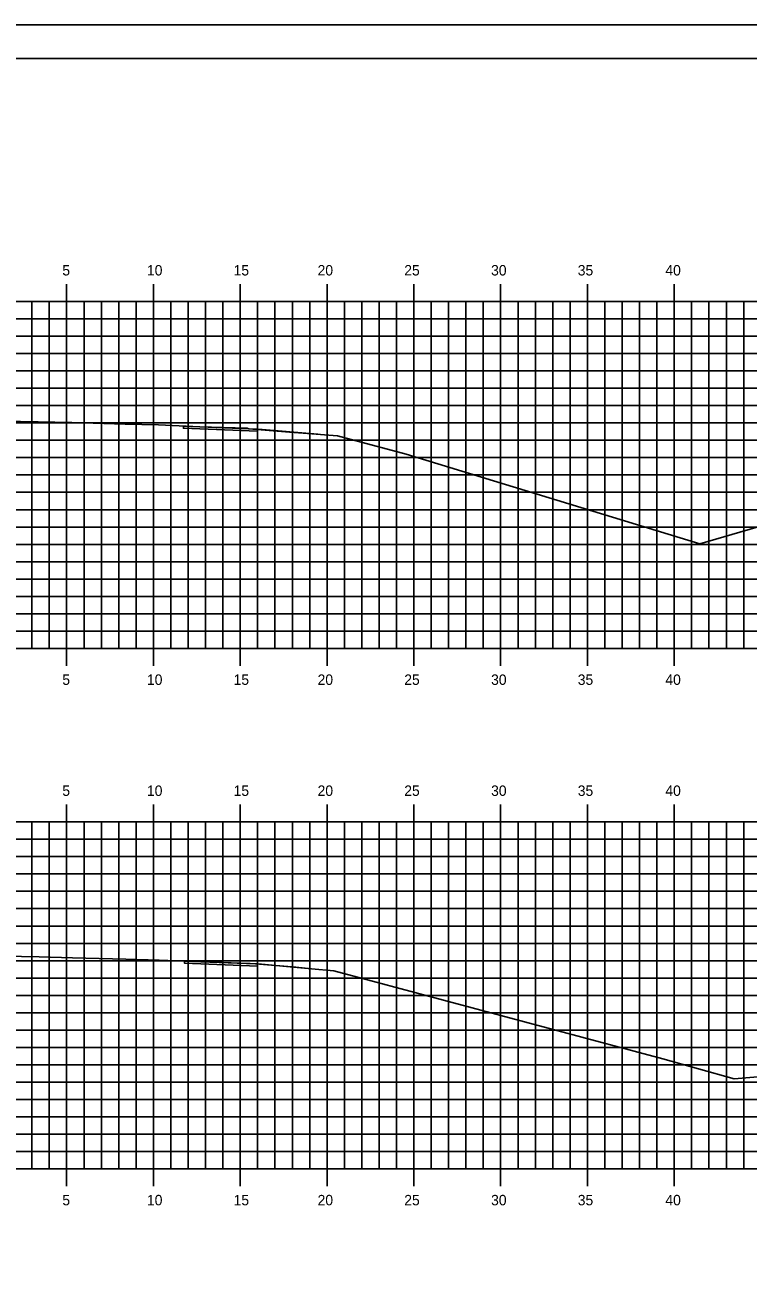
# Model space of a CAD drawing. Extents: x 1168600 to 1177589, y 610178 to 611246.
# Drawn here: x 1177281.8 to 1177323.4, y 610306.8 to 610378.7 of the extents above; entities that cross this region are included whole.
import ezdxf

# ---------------------------------------------------------------- set-up
doc = ezdxf.new("R2010")
doc.units = 0
for name, color, linetype in [('_Construction', 7, 'Continuous'), ('_Station Equation', 7, 'Continuous'), ('D_Roadway_Edge_TW', 7, 'Continuous'), ('D_Text_Standard', 7, 'Continuous'), ('H_V ANNOTATION', 7, 'Continuous'), ('MAJOR', 7, 'Continuous'), ('MINOR', 7, 'Continuous')]:
    doc.layers.add(name, color=color, linetype=linetype)

msp = doc.modelspace()

# ---------------------------------------------------------------- linework, layer by layer
at = {"layer": '_Construction'}
msp.add_line((1177364.168, 610376.801), (1177204.168, 610376.801), dxfattribs=at)
msp.add_lwpolyline([(1177196.074, 610268.742), (1177366.074, 610268.742), (1177366.074, 610378.742), (1177196.074, 610378.742)], close=True, dxfattribs=at)
at = {"layer": '_Station Equation'}
for points in [[(1177279.464, 610355.93), (1177282.534, 610355.863), (1177284.464, 610355.818), (1177287.54, 610355.736), (1177289.464, 610355.684), (1177291.831, 610355.585), (1177294.557, 610355.498), (1177294.667, 610355.465), (1177297.001, 610355.274), (1177298.051, 610355.193), (1177299.771, 610355.064), (1177303.725, 610354.005), (1177320.634, 610348.828), (1177331.513, 610352.01), (1177333.985, 610352.632), (1177338.786, 610353.459), (1177349.168, 610355.791)], [(1177279.503, 610325.085), (1177282.58, 610325.016), (1177284.503, 610324.972), (1177287.586, 610324.887), (1177289.503, 610324.835), (1177292.005, 610324.737), (1177294.736, 610324.649), (1177295.042, 610324.618), (1177297.37, 610324.419), (1177298.278, 610324.323), (1177299.564, 610324.223), (1177318.5, 610319.153), (1177322.626, 610317.983), (1177324.882, 610318.18), (1177335.048, 610320.751), (1177340.269, 610321.981), (1177349.168, 610323.258)]]:
    msp.add_lwpolyline(points, dxfattribs=at)
at = {"layer": 'D_Roadway_Edge_TW'}
for points in [[(1177290.898, 610355.624), (1177294.667, 610355.465), (1177295.168, 610355.443), (1177295.168, 610355.318), (1177290.898, 610355.499), (1177290.898, 610355.624)], [(1177290.898, 610355.624), (1177294.667, 610355.465), (1177295.168, 610355.443), (1177295.168, 610355.318), (1177290.898, 610355.499), (1177290.898, 610355.624)], [(1177290.958, 610324.778), (1177295.042, 610324.618), (1177295.168, 610324.613), (1177295.168, 610324.488), (1177290.958, 610324.653), (1177290.958, 610324.778)], [(1177290.958, 610324.778), (1177295.042, 610324.618), (1177295.168, 610324.613), (1177295.168, 610324.488), (1177290.958, 610324.653), (1177290.958, 610324.778)]]:
    msp.add_lwpolyline(points, dxfattribs=at)
at = {"layer": 'D_Text_Standard'}
for points in [[(1177290.898, 610355.624), (1177290.902, 610355.624), (1177294.668, 610355.465), (1177294.673, 610355.464), (1177295.168, 610355.443), (1177295.202, 610355.443), (1177298.637, 610355.149)], [(1177290.958, 610324.778), (1177291.906, 610324.741), (1177295.043, 610324.618), (1177295.043, 610324.618), (1177295.168, 610324.613), (1177295.172, 610324.613), (1177298.693, 610324.291)]]:
    msp.add_lwpolyline(points, dxfattribs=at)
at = {"layer": 'MAJOR'}
for p, q in [((1177284.168, 610363.803), (1177284.168, 610362.801)), ((1177289.168, 610363.803), (1177289.168, 610362.801)), ((1177294.168, 610363.803), (1177294.168, 610362.801)), ((1177299.168, 610363.803), (1177299.168, 610362.801)), ((1177304.168, 610363.803), (1177304.168, 610362.801)), ((1177309.168, 610363.803), (1177309.168, 610362.801)), ((1177314.168, 610363.803), (1177314.168, 610362.801)), ((1177319.168, 610363.803), (1177319.168, 610362.801)), ((1177209.168, 610362.801), (1177349.168, 610362.801)), ((1177209.168, 610362.801), (1177349.168, 610362.801)), ((1177284.168, 610342.801), (1177284.168, 610362.801)), ((1177289.168, 610342.801), (1177289.168, 610362.801)), ((1177294.168, 610342.801), (1177294.168, 610362.801)), ((1177299.168, 610342.801), (1177299.168, 610362.801)), ((1177304.168, 610342.801), (1177304.168, 610362.801)), ((1177309.168, 610342.801), (1177309.168, 610362.801)), ((1177314.168, 610342.801), (1177314.168, 610362.801)), ((1177319.168, 610342.801), (1177319.168, 610362.801)), ((1177209.168, 610357.801), (1177349.168, 610357.801)), ((1177209.168, 610352.801), (1177349.168, 610352.801)), ((1177209.168, 610347.801), (1177349.168, 610347.801)), ((1177209.168, 610342.801), (1177349.168, 610342.801)), ((1177209.168, 610342.801), (1177349.168, 610342.801)), ((1177284.168, 610341.799), (1177284.168, 610342.801)), ((1177289.168, 610341.799), (1177289.168, 610342.801)), ((1177294.168, 610341.799), (1177294.168, 610342.801)), ((1177299.168, 610341.799), (1177299.168, 610342.801)), ((1177304.168, 610341.799), (1177304.168, 610342.801)), ((1177309.168, 610341.799), (1177309.168, 610342.801)), ((1177314.168, 610341.799), (1177314.168, 610342.801)), ((1177319.168, 610341.799), (1177319.168, 610342.801)), ((1177284.168, 610333.803), (1177284.168, 610332.801)), ((1177289.168, 610333.803), (1177289.168, 610332.801)), ((1177294.168, 610333.803), (1177294.168, 610332.801)), ((1177299.168, 610333.803), (1177299.168, 610332.801)), ((1177304.168, 610333.803), (1177304.168, 610332.801)), ((1177309.168, 610333.803), (1177309.168, 610332.801)), ((1177314.168, 610333.803), (1177314.168, 610332.801)), ((1177319.168, 610333.803), (1177319.168, 610332.801)), ((1177209.168, 610332.801), (1177349.168, 610332.801)), ((1177209.168, 610332.801), (1177349.168, 610332.801)), ((1177284.168, 610312.801), (1177284.168, 610332.801)), ((1177289.168, 610312.801), (1177289.168, 610332.801)), ((1177294.168, 610312.801), (1177294.168, 610332.801)), ((1177299.168, 610312.801), (1177299.168, 610332.801)), ((1177304.168, 610312.801), (1177304.168, 610332.801)), ((1177309.168, 610312.801), (1177309.168, 610332.801)), ((1177314.168, 610312.801), (1177314.168, 610332.801)), ((1177319.168, 610312.801), (1177319.168, 610332.801)), ((1177209.168, 610327.801), (1177349.168, 610327.801)), ((1177209.168, 610322.801), (1177349.168, 610322.801)), ((1177209.168, 610317.801), (1177349.168, 610317.801)), ((1177209.168, 610312.801), (1177349.168, 610312.801)), ((1177209.168, 610312.801), (1177349.168, 610312.801)), ((1177284.168, 610311.799), (1177284.168, 610312.801)), ((1177289.168, 610311.799), (1177289.168, 610312.801)), ((1177294.168, 610311.799), (1177294.168, 610312.801)), ((1177299.168, 610311.799), (1177299.168, 610312.801)), ((1177304.168, 610311.799), (1177304.168, 610312.801)), ((1177309.168, 610311.799), (1177309.168, 610312.801)), ((1177314.168, 610311.799), (1177314.168, 610312.801)), ((1177319.168, 610311.799), (1177319.168, 610312.801))]:
    msp.add_line(p, q, dxfattribs=at)
at = {"layer": 'MINOR'}
for p, q in [((1177282.168, 610342.801), (1177282.168, 610362.801)), ((1177283.168, 610342.801), (1177283.168, 610362.801)), ((1177285.168, 610342.801), (1177285.168, 610362.801)), ((1177286.168, 610342.801), (1177286.168, 610362.801)), ((1177287.168, 610342.801), (1177287.168, 610362.801)), ((1177288.168, 610342.801), (1177288.168, 610362.801)), ((1177290.168, 610342.801), (1177290.168, 610362.801)), ((1177291.168, 610342.801), (1177291.168, 610362.801)), ((1177292.168, 610342.801), (1177292.168, 610362.801)), ((1177293.168, 610342.801), (1177293.168, 610362.801)), ((1177295.168, 610342.801), (1177295.168, 610362.801)), ((1177296.168, 610342.801), (1177296.168, 610362.801)), ((1177297.168, 610342.801), (1177297.168, 610362.801)), ((1177298.168, 610342.801), (1177298.168, 610362.801)), ((1177300.168, 610342.801), (1177300.168, 610362.801)), ((1177301.168, 610342.801), (1177301.168, 610362.801)), ((1177302.168, 610342.801), (1177302.168, 610362.801)), ((1177303.168, 610342.801), (1177303.168, 610362.801)), ((1177305.168, 610342.801), (1177305.168, 610362.801)), ((1177306.168, 610342.801), (1177306.168, 610362.801)), ((1177307.168, 610342.801), (1177307.168, 610362.801)), ((1177308.168, 610342.801), (1177308.168, 610362.801)), ((1177310.168, 610342.801), (1177310.168, 610362.801)), ((1177311.168, 610342.801), (1177311.168, 610362.801)), ((1177312.168, 610342.801), (1177312.168, 610362.801)), ((1177313.168, 610342.801), (1177313.168, 610362.801)), ((1177315.168, 610342.801), (1177315.168, 610362.801)), ((1177316.168, 610342.801), (1177316.168, 610362.801)), ((1177317.168, 610342.801), (1177317.168, 610362.801)), ((1177318.168, 610342.801), (1177318.168, 610362.801)), ((1177320.168, 610342.801), (1177320.168, 610362.801)), ((1177321.168, 610342.801), (1177321.168, 610362.801)), ((1177322.168, 610342.801), (1177322.168, 610362.801)), ((1177323.168, 610342.801), (1177323.168, 610362.801)), ((1177209.168, 610361.801), (1177349.168, 610361.801)), ((1177209.168, 610360.801), (1177349.168, 610360.801)), ((1177209.168, 610359.801), (1177349.168, 610359.801)), ((1177209.168, 610358.801), (1177349.168, 610358.801)), ((1177209.168, 610356.801), (1177349.168, 610356.801)), ((1177209.168, 610355.801), (1177349.168, 610355.801)), ((1177209.168, 610354.801), (1177349.168, 610354.801)), ((1177209.168, 610353.801), (1177349.168, 610353.801)), ((1177209.168, 610351.801), (1177349.168, 610351.801)), ((1177209.168, 610350.801), (1177349.168, 610350.801)), ((1177209.168, 610349.801), (1177349.168, 610349.801)), ((1177209.168, 610348.801), (1177349.168, 610348.801)), ((1177209.168, 610346.801), (1177349.168, 610346.801)), ((1177209.168, 610345.801), (1177349.168, 610345.801)), ((1177209.168, 610344.801), (1177349.168, 610344.801)), ((1177209.168, 610343.801), (1177349.168, 610343.801)), ((1177282.168, 610312.801), (1177282.168, 610332.801)), ((1177283.168, 610312.801), (1177283.168, 610332.801)), ((1177285.168, 610312.801), (1177285.168, 610332.801)), ((1177286.168, 610312.801), (1177286.168, 610332.801)), ((1177287.168, 610312.801), (1177287.168, 610332.801)), ((1177288.168, 610312.801), (1177288.168, 610332.801)), ((1177290.168, 610312.801), (1177290.168, 610332.801)), ((1177291.168, 610312.801), (1177291.168, 610332.801)), ((1177292.168, 610312.801), (1177292.168, 610332.801)), ((1177293.168, 610312.801), (1177293.168, 610332.801)), ((1177295.168, 610312.801), (1177295.168, 610332.801)), ((1177296.168, 610312.801), (1177296.168, 610332.801)), ((1177297.168, 610312.801), (1177297.168, 610332.801)), ((1177298.168, 610312.801), (1177298.168, 610332.801)), ((1177300.168, 610312.801), (1177300.168, 610332.801)), ((1177301.168, 610312.801), (1177301.168, 610332.801)), ((1177302.168, 610312.801), (1177302.168, 610332.801)), ((1177303.168, 610312.801), (1177303.168, 610332.801)), ((1177305.168, 610312.801), (1177305.168, 610332.801)), ((1177306.168, 610312.801), (1177306.168, 610332.801)), ((1177307.168, 610312.801), (1177307.168, 610332.801)), ((1177308.168, 610312.801), (1177308.168, 610332.801)), ((1177310.168, 610312.801), (1177310.168, 610332.801)), ((1177311.168, 610312.801), (1177311.168, 610332.801)), ((1177312.168, 610312.801), (1177312.168, 610332.801)), ((1177313.168, 610312.801), (1177313.168, 610332.801)), ((1177315.168, 610312.801), (1177315.168, 610332.801)), ((1177316.168, 610312.801), (1177316.168, 610332.801)), ((1177317.168, 610312.801), (1177317.168, 610332.801)), ((1177318.168, 610312.801), (1177318.168, 610332.801)), ((1177320.168, 610312.801), (1177320.168, 610332.801)), ((1177321.168, 610312.801), (1177321.168, 610332.801)), ((1177322.168, 610312.801), (1177322.168, 610332.801)), ((1177323.168, 610312.801), (1177323.168, 610332.801)), ((1177209.168, 610331.801), (1177349.168, 610331.801)), ((1177209.168, 610330.801), (1177349.168, 610330.801)), ((1177209.168, 610329.801), (1177349.168, 610329.801)), ((1177209.168, 610328.801), (1177349.168, 610328.801)), ((1177209.168, 610326.801), (1177349.168, 610326.801)), ((1177209.168, 610325.801), (1177349.168, 610325.801)), ((1177209.168, 610324.801), (1177349.168, 610324.801)), ((1177209.168, 610323.801), (1177349.168, 610323.801)), ((1177209.168, 610321.801), (1177349.168, 610321.801)), ((1177209.168, 610320.801), (1177349.168, 610320.801)), ((1177209.168, 610319.801), (1177349.168, 610319.801)), ((1177209.168, 610318.801), (1177349.168, 610318.801)), ((1177209.168, 610316.801), (1177349.168, 610316.801)), ((1177209.168, 610315.801), (1177349.168, 610315.801)), ((1177209.168, 610314.801), (1177349.168, 610314.801)), ((1177209.168, 610313.801), (1177349.168, 610313.801))]:
    msp.add_line(p, q, dxfattribs=at)

# ---------------------------------------------------------------- texts
at = {"layer": 'H_V ANNOTATION'}
for s, p in [('5', (1177283.919, 610364.301)), ('10', (1177288.793, 610364.301)), ('15', (1177293.785, 610364.301)), ('20', (1177298.622, 610364.301)), ('25', (1177303.614, 610364.301)), ('30', (1177308.616, 610364.301)), ('35', (1177313.608, 610364.301)), ('40', (1177318.654, 610364.301)), ('5', (1177283.919, 610340.701)), ('10', (1177288.793, 610340.701)), ('15', (1177293.785, 610340.701)), ('20', (1177298.622, 610340.701)), ('25', (1177303.614, 610340.701)), ('30', (1177308.616, 610340.701)), ('35', (1177313.608, 610340.701)), ('40', (1177318.654, 610340.701)), ('5', (1177283.919, 610334.301)), ('10', (1177288.793, 610334.301)), ('15', (1177293.785, 610334.301)), ('20', (1177298.622, 610334.301)), ('25', (1177303.614, 610334.301)), ('30', (1177308.616, 610334.301)), ('35', (1177313.608, 610334.301)), ('40', (1177318.654, 610334.301)), ('5', (1177283.919, 610310.701)), ('10', (1177288.793, 610310.701)), ('15', (1177293.785, 610310.701)), ('20', (1177298.622, 610310.701)), ('25', (1177303.614, 610310.701)), ('30', (1177308.616, 610310.701)), ('35', (1177313.608, 610310.701)), ('40', (1177318.654, 610310.701))]:
    msp.add_text(s, height=0.6, dxfattribs=at).set_placement(p)

doc.saveas('drawing.dxf')
